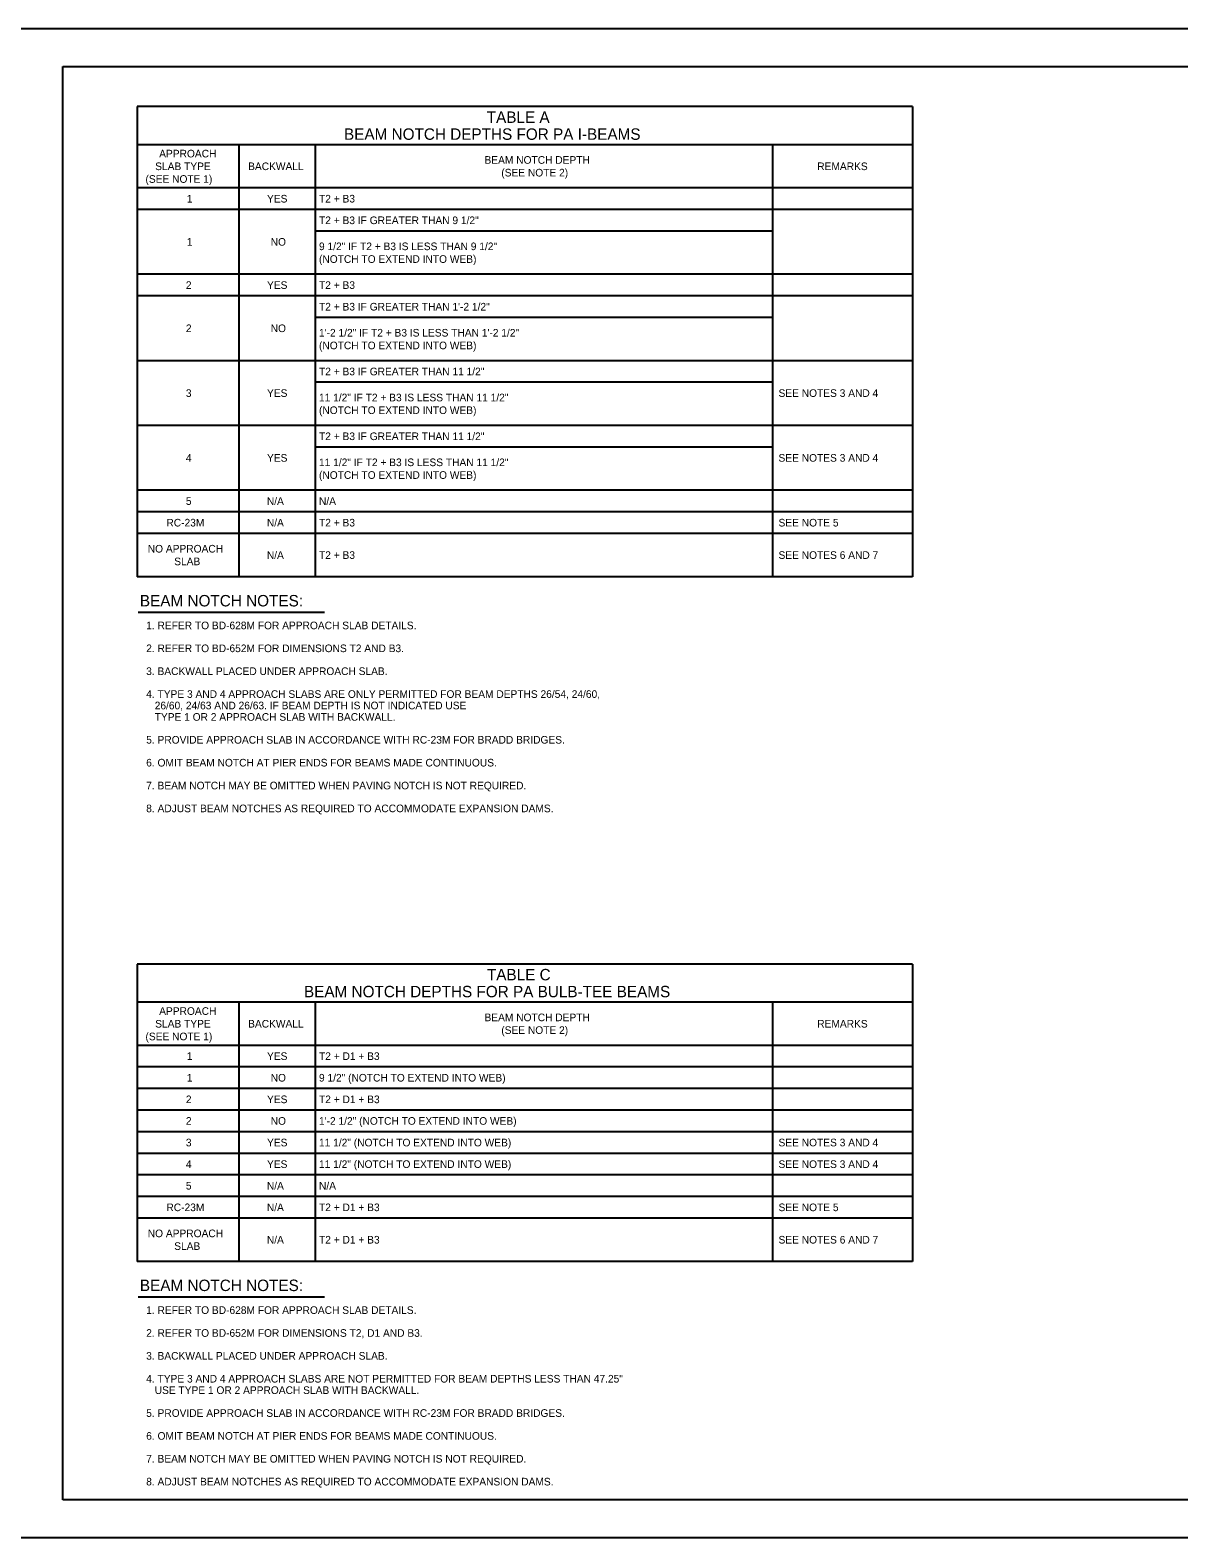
# Model space of a CAD drawing. Extents: x 637933 to 640019, y 298854 to 300042.
# Drawn here: x 638852 to 639304, y 298854 to 299447 of the extents above; entities that cross this region are included whole.
import ezdxf

# ---------------------------------------------------------------- set-up
doc = ezdxf.new("R2010")
doc.units = 0
doc.layers.add('1', color=7, linetype='Continuous')
doc.layers.add('PLT-BNDY', color=7, linetype='Continuous')

msp = doc.modelspace()

# ---------------------------------------------------------------- linework, layer by layer
at = {"layer": '1'}
for p, q in [((638864.93, 298869.12), (638864.93, 299433.14)), ((638864.93, 298869.12), (638864.93, 299433.12)), ((638864.93, 299433.12), (639650.94, 299433.12)), ((639199.17, 299417.39), (638894.17, 299417.39)), ((638894.17, 299417.39), (638894.17, 299232.39)), ((639199.17, 299417.39), (639199.17, 299232.39)), ((639199.17, 299402.39), (638894.17, 299402.39)), ((638934.17, 299402.39), (638934.17, 299232.39)), ((638964.17, 299402.39), (638964.17, 299232.39)), ((639144.17, 299402.39), (639144.17, 299232.39)), ((639199.17, 299385.39), (638894.17, 299385.39)), ((639199.17, 299376.89), (638894.17, 299376.89)), ((639144.17, 299368.39), (638964.17, 299368.39)), ((639199.17, 299351.39), (638894.17, 299351.39)), ((639199.17, 299342.89), (638894.17, 299342.89)), ((639144.17, 299334.39), (638964.17, 299334.39)), ((639199.17, 299317.39), (638894.17, 299317.39)), ((639144.17, 299308.89), (638964.17, 299308.89)), ((639199.17, 299291.89), (638894.17, 299291.89)), ((639144.17, 299283.39), (638964.17, 299283.39)), ((639199.17, 299266.39), (638894.17, 299266.39)), ((639199.17, 299257.89), (638894.17, 299257.89)), ((639199.17, 299249.39), (638894.17, 299249.39)), ((639199.17, 299232.39), (638894.17, 299232.39)), ((638894.49, 299218.37), (638967.92, 299218.37)), ((639199.17, 299079.94), (638894.17, 299079.94)), ((638894.17, 299079.94), (638894.17, 298962.94)), ((639199.17, 299079.94), (639199.17, 298962.94)), ((639199.17, 299064.94), (638894.17, 299064.94)), ((638934.17, 299064.94), (638934.17, 298962.94)), ((638964.17, 299064.94), (638964.17, 298962.94)), ((639144.17, 299064.94), (639144.17, 298962.94)), ((639199.17, 299047.94), (638894.17, 299047.94)), ((639199.17, 299039.44), (638894.17, 299039.44)), ((639199.17, 299030.94), (638894.17, 299030.94)), ((639199.17, 299022.44), (638894.17, 299022.44)), ((639199.17, 299013.94), (638894.17, 299013.94)), ((639199.17, 299005.44), (638894.17, 299005.44)), ((639199.17, 298996.94), (638894.17, 298996.94)), ((639199.17, 298988.44), (638894.17, 298988.44)), ((639199.17, 298979.94), (638894.17, 298979.94)), ((639199.17, 298962.94), (638894.17, 298962.94)), ((638894.49, 298948.92), (638967.92, 298948.92)), ((639650.94, 298869.12), (638864.93, 298869.12))]:
    msp.add_line(p, q, dxfattribs=at)
at = {"layer": 'PLT-BNDY'}
msp.add_lwpolyline([(638824.93, 299448.12), (639665.93, 299448.12), (639665.93, 298854.12), (638824.93, 298854.12)], close=True, dxfattribs=at)

# ---------------------------------------------------------------- texts
at = {"layer": '1'}
for s, height, p in [('TABLE A', 4.5, (639031.7, 299410.97)), ('BEAM NOTCH DEPTHS FOR PA I-BEAMS', 4.5, (638975.54, 299404.31)), ('T2 + B3', 3, (638965.7, 299379.64)), ('T2 + B3 IF GREATER THAN 9 1/2"', 3, (638965.7, 299371.14)), ('9 1/2" IF T2 + B3 IS LESS THAN 9 1/2"', 3, (638965.7, 299360.89)), ('(NOTCH TO EXTEND INTO WEB)', 3, (638965.7, 299355.89)), ('T2 + B3', 3, (638965.7, 299345.64)), ('T2 + B3 IF GREATER THAN 1\'-2 1/2"', 3, (638965.7, 299337.14)), ('1\'-2 1/2" IF T2 + B3 IS LESS THAN 1\'-2 1/2"', 3, (638965.7, 299326.89)), ('(NOTCH TO EXTEND INTO WEB)', 3, (638965.7, 299321.89)), ('T2 + B3 IF GREATER THAN 11 1/2"', 3, (638965.7, 299311.64)), ('11 1/2" IF T2 + B3 IS LESS THAN 11 1/2"', 3, (638965.7, 299301.39)), ('SEE NOTES 3 AND 4', 3, (639146.51, 299303.14)), ('(NOTCH TO EXTEND INTO WEB)', 3, (638965.7, 299296.39)), ('T2 + B3 IF GREATER THAN 11 1/2"', 3, (638965.7, 299286.14)), ('SEE NOTES 3 AND 4', 3, (639146.51, 299277.64)), ('11 1/2" IF T2 + B3 IS LESS THAN 11 1/2"', 3, (638965.7, 299275.89)), ('(NOTCH TO EXTEND INTO WEB)', 3, (638965.7, 299270.89)), ('N/A', 3, (638965.7, 299260.64)), ('T2 + B3', 3, (638965.7, 299252.14)), ('SEE NOTE 5', 3, (639146.51, 299252.14)), ('T2 + B3', 3, (638965.7, 299239.39)), ('SEE NOTES 6 AND 7', 3, (639146.51, 299239.39)), ('BEAM NOTCH NOTES:', 4.5, (638895.23, 299220.68)), (' 1. REFER TO BD-628M FOR APPROACH SLAB DETAILS.', 3, (638896.6, 299211.69)), (' 2. REFER TO BD-652M FOR DIMENSIONS T2 AND B3.', 3, (638896.6, 299202.69)), (' 3. BACKWALL PLACED UNDER APPROACH SLAB.', 3, (638896.6, 299193.69)), (' 4. TYPE 3 AND 4 APPROACH SLABS ARE ONLY PERMITTED FOR BEAM DEPTHS 26/54, 24/60,', 3, (638896.6, 299184.69)), ('    26/60, 24/63 AND 26/63. IF BEAM DEPTH IS NOT INDICATED USE', 3, (638896.6, 299180.19)), ('    TYPE 1 OR 2 APPROACH SLAB WITH BACKWALL.', 3, (638896.6, 299175.69)), (' 5. PROVIDE APPROACH SLAB IN ACCORDANCE WITH RC-23M FOR BRADD BRIDGES.', 3, (638896.6, 299166.69)), (' 6. OMIT BEAM NOTCH AT PIER ENDS FOR BEAMS MADE CONTINUOUS.', 3, (638896.6, 299157.69)), (' 7. BEAM NOTCH MAY BE OMITTED WHEN PAVING NOTCH IS NOT REQUIRED.', 3, (638896.6, 299148.69)), (' 8. ADJUST BEAM NOTCHES AS REQUIRED TO ACCOMMODATE EXPANSION DAMS.', 3, (638896.6, 299139.69)), ('TABLE C', 4.5, (639031.77, 299073.52)), ('BEAM NOTCH DEPTHS FOR PA BULB-TEE BEAMS', 4.5, (638959.79, 299066.86)), ('T2 + D1 + B3', 3, (638965.7, 299042.19)), ('9 1/2" (NOTCH TO EXTEND INTO WEB)', 3, (638965.7, 299033.69)), ('T2 + D1 + B3', 3, (638965.7, 299025.19)), ('1\'-2 1/2" (NOTCH TO EXTEND INTO WEB)', 3, (638965.7, 299016.69)), ('11 1/2" (NOTCH TO EXTEND INTO WEB)', 3, (638965.7, 299008.19)), ('SEE NOTES 3 AND 4', 3, (639146.51, 299008.19)), ('11 1/2" (NOTCH TO EXTEND INTO WEB)', 3, (638965.7, 298999.69)), ('SEE NOTES 3 AND 4', 3, (639146.51, 298999.69)), ('N/A', 3, (638965.7, 298991.19)), ('T2 + D1 + B3', 3, (638965.7, 298982.69)), ('SEE NOTE 5', 3, (639146.51, 298982.69)), ('T2 + D1 + B3', 3, (638965.7, 298969.94)), ('SEE NOTES 6 AND 7', 3, (639146.51, 298969.94)), ('BEAM NOTCH NOTES:', 4.5, (638895.23, 298951.24)), (' 1. REFER TO BD-628M FOR APPROACH SLAB DETAILS.', 3, (638896.6, 298942.24)), (' 2. REFER TO BD-652M FOR DIMENSIONS T2, D1 AND B3.', 3, (638896.6, 298933.24)), (' 3. BACKWALL PLACED UNDER APPROACH SLAB.', 3, (638896.6, 298924.24)), (' 4. TYPE 3 AND 4 APPROACH SLABS ARE NOT PERMITTED FOR BEAM DEPTHS LESS THAN 47.25"', 3, (638896.6, 298915.24)), ('    USE TYPE 1 OR 2 APPROACH SLAB WITH BACKWALL.', 3, (638896.6, 298910.74)), (' 5. PROVIDE APPROACH SLAB IN ACCORDANCE WITH RC-23M FOR BRADD BRIDGES.', 3, (638896.6, 298901.74)), (' 6. OMIT BEAM NOTCH AT PIER ENDS FOR BEAMS MADE CONTINUOUS.', 3, (638896.6, 298892.74)), (' 7. BEAM NOTCH MAY BE OMITTED WHEN PAVING NOTCH IS NOT REQUIRED.', 3, (638896.6, 298883.74)), (' 8. ADJUST BEAM NOTCHES AS REQUIRED TO ACCOMMODATE EXPANSION DAMS.', 3, (638896.6, 298874.74))]:
    msp.add_text(s, height=height, dxfattribs=at).set_placement(p)
for s, p in [('APPROACH', (638902.82, 299397.39)), ('SLAB TYPE', (638901.25, 299392.39)), ('BACKWALL', (638937.82, 299392.39)), ('BEAM NOTCH DEPTH', (639030.82, 299394.89)), ('REMARKS', (639161.75, 299392.39)), ('(SEE NOTE 1)', (638897.43, 299387.39)), ('(SEE NOTE 2)', (639037.43, 299389.89)), ('1', (638913.66, 299379.64)), ('YES', (638945.25, 299379.64)), ('1', (638913.66, 299362.64)), ('NO', (638946.69, 299362.64)), ('2', (638913.32, 299345.64)), ('YES', (638945.25, 299345.64)), ('2', (638913.32, 299328.64)), ('NO', (638946.69, 299328.64)), ('3', (638913.32, 299303.14)), ('YES', (638945.25, 299303.14)), ('4', (638913.32, 299277.64)), ('YES', (638945.25, 299277.64)), ('5', (638913.32, 299260.64)), ('N/A', (638945.19, 299260.64)), ('RC-23M', (638905.66, 299252.14)), ('N/A', (638945.19, 299252.14)), ('NO APPROACH', (638898.32, 299241.89)), ('SLAB', (638908.73, 299236.89)), ('N/A', (638945.19, 299239.39)), ('APPROACH', (638902.82, 299059.94)), ('SLAB TYPE', (638901.25, 299054.94)), ('BACKWALL', (638937.82, 299054.94)), ('BEAM NOTCH DEPTH', (639030.82, 299057.44)), ('(SEE NOTE 2)', (639037.43, 299052.44)), ('REMARKS', (639161.75, 299054.94)), ('(SEE NOTE 1)', (638897.43, 299049.94)), ('1', (638913.66, 299042.19)), ('YES', (638945.25, 299042.19)), ('1', (638913.66, 299033.69)), ('NO', (638946.69, 299033.69)), ('2', (638913.32, 299025.19)), ('YES', (638945.25, 299025.19)), ('2', (638913.32, 299016.69)), ('NO', (638946.69, 299016.69)), ('3', (638913.32, 299008.19)), ('YES', (638945.25, 299008.19)), ('4', (638913.32, 298999.69)), ('YES', (638945.25, 298999.69)), ('5', (638913.32, 298991.19)), ('N/A', (638945.19, 298991.19)), ('RC-23M', (638905.66, 298982.69)), ('N/A', (638945.19, 298982.69)), ('NO APPROACH', (638898.32, 298972.44)), ('N/A', (638945.19, 298969.94)), ('SLAB', (638908.73, 298967.44))]:
    msp.add_text(s, height=3, rotation=360, dxfattribs=at).set_placement(p)

doc.saveas('drawing.dxf')
